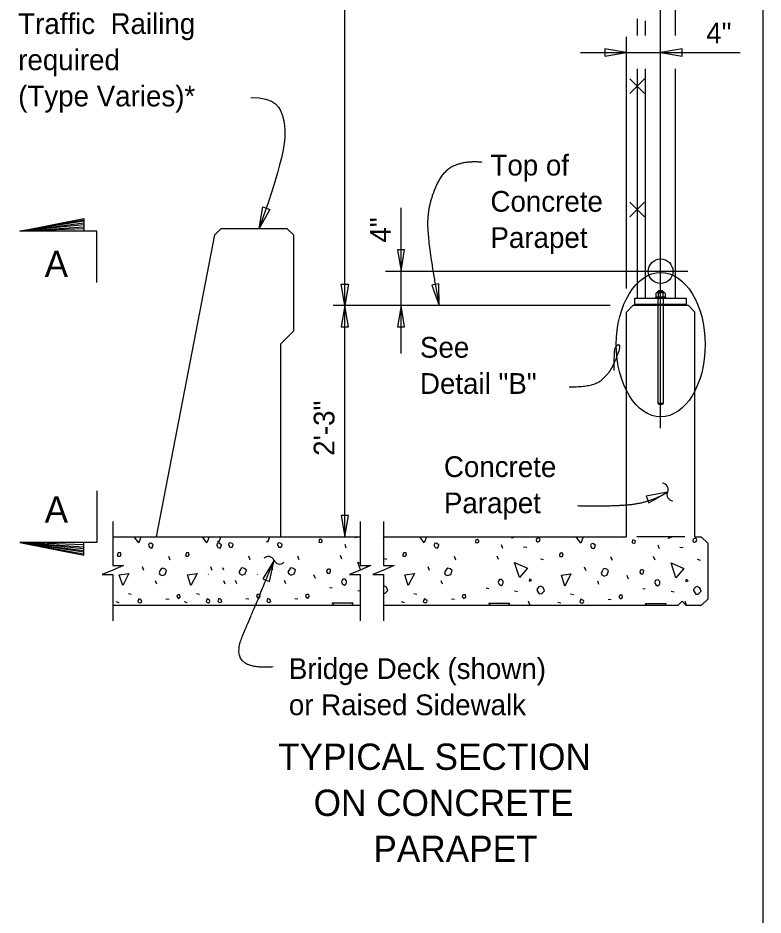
# Model space of a CAD drawing. Extents: x 0 to 72.1, y -15.2 to 30.1.
# Drawn here: x 33.82 to 41.07, y 12.6 to 21.32 of the extents above; entities that cross this region are included whole.
import ezdxf

# ---------------------------------------------------------------- set-up
doc = ezdxf.new("R2010")
doc.units = 0
for name, color, linetype in [('ActivePts-ConstElements', 7, 'Continuous'), ('AdhocPoint_dp', 7, 'Continuous'), ('Border', 7, 'Continuous'), ('Patterning', 7, 'Continuous'), ('PlotBorder_dp', 7, 'Continuous'), ('SheetBorder_dp', 7, 'Continuous'), ('SheetLines_dp', 7, 'Continuous'), ('SupstrConc_h', 7, 'Continuous'), ('TextMisc', 7, 'Continuous')]:
    doc.layers.add(name, color=color, linetype=linetype)

# ---------------------------------------------------------------- blocks, each defined once
blk = doc.blocks.new('Terminator-Arrow')
at = {"layer": 'PlotBorder_dp'}
blk.add_lwpolyline([(0, 0), (-0.00041, 0.000069), (-0.00041, -0.000069), (0, 0)], dxfattribs=at)
blk.add_lwpolyline([(0, 0), (-0.00041, 0.000069), (-0.00041, -0.000069)], close=True, dxfattribs=at)

msp = doc.modelspace()

# ---------------------------------------------------------------- linework, layer by layer
at = {"layer": 'ActivePts-ConstElements'}
msp.add_lwpolyline([(0.016, 2.0538), (41.0666, 2.0538), (41.0666, 27.9999), (0.016, 27.9999)], close=True, dxfattribs=at)
at = {"layer": 'AdhocPoint_dp'}
for p, q in [((39.7989, 18.5283), (39.7364, 18.465)), ((40.3405, 18.5283), (39.7989, 18.5283)), ((40.3405, 18.5283), (39.7989, 18.5283)), ((40.3405, 18.5283), (40.4031, 18.465)), ((39.7364, 16.2784), (39.7364, 18.465)), ((40.4031, 16.2784), (40.4031, 18.465)), ((34.7399, 16.2784), (37.1456, 16.2784)), ((37.3729, 16.2784), (39.7364, 16.2784)), ((40.4031, 16.2784), (40.4656, 16.2784)), ((40.4656, 16.2784), (40.5281, 16.2159)), ((40.5281, 16.2159), (40.5281, 15.6742)), ((40.2364, 15.6117), (40.2781, 15.6533)), ((40.2781, 15.6533), (40.3198, 15.6117)), ((40.5281, 15.6742), (40.4656, 15.6117)), ((40.2364, 15.6117), (37.3729, 15.6117)), ((40.4656, 15.6117), (40.3198, 15.6117))]:
    msp.add_line(p, q, dxfattribs=at)
at = {"layer": 'Border'}
for p, q in [((40.0437, 18.6013), (40.0437, 17.5781)), ((40.0958, 18.6013), (40.0958, 17.5781)), ((40.0437, 17.5781), (40.0958, 17.5781)), ((40.0437, 17.5781), (40.0519, 17.57)), ((40.0519, 17.57), (40.0876, 17.57)), ((40.0958, 17.5781), (40.0876, 17.57))]:
    msp.add_line(p, q, dxfattribs=at)
at = {"layer": 'Patterning'}
for p, q in [((39.9112, 20.7323), (39.7698, 20.5911)), ((39.7698, 20.7323), (39.9112, 20.5911)), ((39.9112, 19.5323), (39.7698, 19.3911)), ((39.7698, 19.5323), (39.9112, 19.3911)), ((40.0586, 18.6707), (40.0793, 18.6707)), ((40.0586, 18.661), (40.0793, 18.661)), ((39.8197, 18.5353), (40.3197, 18.5353)), ((39.8197, 18.5318), (40.3197, 18.5318)), ((35.4069, 16.2784), (35.4083, 16.2781)), ((38.185, 16.2784), (38.1863, 16.2781)), ((39.6911, 16.2784), (39.7101, 16.2746)), ((37.0108, 16.1703), (36.9984, 16.2039)), ((38.5346, 16.1667), (38.5222, 16.2003)), ((38.7343, 16.1826), (38.7662, 16.1791)), ((40.0584, 16.1632), (40.046, 16.1968)), ((40.2581, 16.1791), (40.29, 16.1756)), ((35.2987, 16.0518), (35.2845, 16.0872)), ((36.0762, 16.0554), (36.0621, 16.0907)), ((36.5529, 16.0554), (36.5388, 16.0907)), ((36.9683, 16.0607), (36.9542, 16.096)), ((37.3785, 16.0677), (37.4067, 16.0607)), ((38.0767, 16.0518), (38.0626, 16.0872)), ((38.4922, 16.0571), (38.478, 16.0925)), ((38.9023, 16.0642), (38.9306, 16.0571)), ((39.6005, 16.0483), (39.5864, 16.0836)), ((40.016, 16.0536), (40.0018, 16.0889)), ((40.4261, 16.0607), (40.4544, 16.0536)), ((35.0424, 15.9511), (35.0282, 15.9864)), ((35.7059, 15.9511), (35.6917, 15.9864)), ((35.8199, 15.9546), (35.8104, 15.9783)), ((36.2966, 15.9546), (36.2871, 15.9783)), ((37.8204, 15.9511), (37.8063, 15.9864)), ((39.3442, 15.9475), (39.3301, 15.9829)), ((36.7102, 15.8733), (36.6961, 15.9086)), ((39.7579, 15.8662), (39.7437, 15.9016)), ((35.1679, 15.8185), (35.1555, 15.8521)), ((35.8314, 15.8185), (35.819, 15.8521)), ((35.9454, 15.822), (35.933, 15.8556)), ((36.4221, 15.822), (36.4097, 15.8556)), ((37.9459, 15.8185), (37.9335, 15.8521)), ((39.4697, 15.8149), (39.4573, 15.8485)), ((34.8903, 15.7283), (34.9186, 15.7213)), ((35.5538, 15.7283), (35.5821, 15.7213)), ((36.8481, 15.7849), (36.8729, 15.7814)), ((37.1239, 15.7566), (37.1456, 15.7528)), ((37.6684, 15.7283), (37.6967, 15.7213)), ((38.3719, 15.7814), (38.3967, 15.7778)), ((38.6477, 15.7531), (38.6778, 15.7478)), ((39.1922, 15.7248), (39.2205, 15.7177)), ((39.8958, 15.7778), (39.9205, 15.7743)), ((40.1715, 15.7495), (40.2016, 15.7442)), ((34.7684, 15.6488), (34.7966, 15.6417)), ((35.2563, 15.6771), (35.2863, 15.6718)), ((35.4319, 15.6488), (35.4601, 15.6417)), ((36.0338, 15.6806), (36.0639, 15.6753)), ((36.5105, 15.6806), (36.5405, 15.6753)), ((37.5464, 15.6488), (37.5747, 15.6417)), ((38.0343, 15.6771), (38.0644, 15.6718)), ((38.7962, 15.6187), (38.7838, 15.6523)), ((39.0702, 15.6452), (39.0985, 15.6382)), ((39.5581, 15.6735), (39.5882, 15.6682)), ((40.32, 15.6152), (40.3076, 15.6488))]:
    msp.add_line(p, q, dxfattribs=at)
for points in [[(39.8406, 21.3159), (39.8406, 21.1537)], [(39.8406, 20.8291), (39.8406, 18.6013)], [(34.9911, 16.2215), (34.9479, 16.2784)], [(35.0123, 16.2784), (34.9911, 16.2215)], [(35.6546, 16.2215), (35.6114, 16.2784)], [(35.6758, 16.2784), (35.6546, 16.2215)], [(35.7686, 16.2251), (35.7598, 16.2367)], [(35.7886, 16.2784), (35.7686, 16.2251)], [(36.2453, 16.2251), (36.2365, 16.2367)], [(36.2652, 16.2784), (36.2453, 16.2251)], [(36.7438, 16.2286), (36.7633, 16.2233), (36.7757, 16.2321), (36.7774, 16.2445), (36.7739, 16.248), (36.7597, 16.2551), (36.7474, 16.2534), (36.7456, 16.241), (36.7438, 16.2286)], [(37.0992, 16.2693), (37.102, 16.2784)], [(37.1194, 16.2784), (37.0992, 16.2693)], [(37.3729, 16.2562), (37.3732, 16.2569), (37.3729, 16.2581)], [(37.7691, 16.2215), (37.7259, 16.2784)], [(37.7904, 16.2784), (37.7691, 16.2215)], [(38.2676, 16.2251), (38.2871, 16.2198), (38.2995, 16.2286), (38.3012, 16.241), (38.2977, 16.2445), (38.2836, 16.2516), (38.2712, 16.2498), (38.2694, 16.2374), (38.2676, 16.2251)], [(38.623, 16.2657), (38.6269, 16.2784)], [(38.6511, 16.2784), (38.623, 16.2657)], [(38.8705, 16.2304), (38.8775, 16.2304), (38.8917, 16.2374), (38.897, 16.2534), (38.8952, 16.2622), (38.8811, 16.2693), (38.8634, 16.2587), (38.8598, 16.248), (38.8634, 16.2374), (38.8705, 16.2304)], [(39.2929, 16.218), (39.2471, 16.2784)], [(39.3155, 16.2784), (39.2929, 16.218)], [(39.7915, 16.2215), (39.8109, 16.2162), (39.8233, 16.2251), (39.825, 16.2374), (39.8215, 16.241), (39.8074, 16.248), (39.795, 16.2463), (39.7932, 16.2339), (39.7915, 16.2215)], [(40.1468, 16.2622), (40.1518, 16.2784)], [(40.1828, 16.2784), (40.1468, 16.2622)], [(40.3943, 16.2268), (40.4013, 16.2268), (40.4155, 16.2339), (40.4208, 16.2498), (40.419, 16.2587), (40.4049, 16.2657), (40.3872, 16.2551), (40.3837, 16.2445), (40.3872, 16.2339), (40.3943, 16.2268)], [(35.0901, 16.1897), (35.0989, 16.1738), (35.1201, 16.1703), (35.129, 16.1862), (35.1325, 16.2003), (35.1237, 16.2092), (35.1078, 16.218), (35.0919, 16.2127), (35.0866, 16.1968), (35.0901, 16.1897)], [(35.7536, 16.1897), (35.7624, 16.1738), (35.7836, 16.1703), (35.7925, 16.1862), (35.796, 16.2003), (35.7872, 16.2092), (35.7713, 16.218), (35.7554, 16.2127), (35.7501, 16.1968), (35.7536, 16.1897)], [(35.8676, 16.1932), (35.8765, 16.1773), (35.8977, 16.1738), (35.9065, 16.1897), (35.9101, 16.2039), (35.9012, 16.2127), (35.8853, 16.2215), (35.8694, 16.2162), (35.8641, 16.2003), (35.8676, 16.1932)], [(36.3443, 16.1932), (36.3532, 16.1773), (36.3744, 16.1738), (36.3832, 16.1897), (36.3867, 16.2039), (36.3779, 16.2127), (36.362, 16.2215), (36.3461, 16.2162), (36.3408, 16.2003), (36.3443, 16.1932)], [(37.8681, 16.1897), (37.877, 16.1738), (37.8982, 16.1703), (37.907, 16.1862), (37.9106, 16.2003), (37.9017, 16.2092), (37.8858, 16.218), (37.8699, 16.2127), (37.8646, 16.1968), (37.8681, 16.1897)], [(39.3919, 16.1862), (39.4008, 16.1703), (39.422, 16.1667), (39.4308, 16.1826), (39.4344, 16.1968), (39.4255, 16.2056), (39.4096, 16.2145), (39.3937, 16.2092), (39.3884, 16.1932), (39.3919, 16.1862)], [(34.7878, 16.0925), (34.809, 16.0925), (34.8196, 16.1031), (34.8143, 16.1225), (34.7913, 16.1243), (34.7878, 16.1137), (34.7825, 16.1049), (34.7878, 16.0925), (34.7843, 16.096)], [(35.4513, 16.0925), (35.4725, 16.0925), (35.4831, 16.1031), (35.4778, 16.1225), (35.4548, 16.1243), (35.4513, 16.1137), (35.446, 16.1049), (35.4513, 16.0925), (35.4478, 16.096)], [(37.5658, 16.0925), (37.5871, 16.0925), (37.5977, 16.1031), (37.5924, 16.1225), (37.5694, 16.1243), (37.5658, 16.1137), (37.5605, 16.1049), (37.5658, 16.0925), (37.5623, 16.096)], [(39.0897, 16.0889), (39.1109, 16.0889), (39.1215, 16.0996), (39.1162, 16.119), (39.0932, 16.1208), (39.0897, 16.1102), (39.0844, 16.1013), (39.0897, 16.0889), (39.0861, 16.0925)], [(35.1962, 15.9139), (35.2191, 15.9016), (35.2492, 15.9139), (35.2616, 15.9511), (35.2439, 15.9687), (35.2209, 15.974), (35.2103, 15.967), (35.1979, 15.9475), (35.1891, 15.9316), (35.1962, 15.9139)], [(35.9737, 15.9175), (35.9967, 15.9051), (36.0267, 15.9175), (36.0391, 15.9546), (36.0214, 15.9723), (35.9984, 15.9776), (35.9878, 15.9705), (35.9755, 15.9511), (35.9666, 15.9352), (35.9737, 15.9175)], [(36.4504, 15.9175), (36.4734, 15.9051), (36.5034, 15.9175), (36.5158, 15.9546), (36.4981, 15.9723), (36.4751, 15.9776), (36.4645, 15.9705), (36.4522, 15.9511), (36.4433, 15.9352), (36.4504, 15.9175)], [(37.1483, 15.9574), (37.1239, 16.0324), (37.1456, 16.0229)], [(37.1952, 16.0012), (37.222, 15.9895)], [(37.9742, 15.9139), (37.9972, 15.9016), (38.0272, 15.9139), (38.0396, 15.9511), (38.0219, 15.9687), (37.9989, 15.974), (37.9883, 15.967), (37.976, 15.9475), (37.9671, 15.9316), (37.9742, 15.9139)], [(38.6954, 15.8821), (38.6477, 16.0288), (38.7732, 15.974), (38.6954, 15.8821)], [(39.498, 15.9104), (39.521, 15.898), (39.551, 15.9104), (39.5634, 15.9475), (39.5457, 15.9652), (39.5228, 15.9705), (39.5122, 15.9634), (39.4998, 15.944), (39.4909, 15.9281), (39.498, 15.9104)], [(40.2193, 15.8786), (40.1715, 16.0253), (40.297, 15.9705), (40.2193, 15.8786)], [(34.8355, 15.8043), (34.8019, 15.9086), (34.8956, 15.921), (34.8355, 15.8043)], [(35.499, 15.8043), (35.4654, 15.9086), (35.5591, 15.921), (35.499, 15.8043)], [(35.6692, 15.9168), (35.6663, 15.9112)], [(36.1459, 15.9168), (36.143, 15.9112)], [(36.8198, 15.9405), (36.8287, 15.9245), (36.8481, 15.9263), (36.857, 15.9387), (36.8587, 15.9581), (36.8464, 15.9634), (36.8375, 15.9652), (36.8269, 15.9617), (36.8234, 15.9581), (36.8198, 15.9405)], [(37.6136, 15.8043), (37.58, 15.9086), (37.6737, 15.921), (37.6136, 15.8043)], [(39.1374, 15.8008), (39.1038, 15.9051), (39.1975, 15.9175), (39.1374, 15.8008)], [(39.8675, 15.9334), (39.8763, 15.9175), (39.8958, 15.9192), (39.9046, 15.9316), (39.9064, 15.9511), (39.894, 15.9564), (39.8851, 15.9581), (39.8745, 15.9546), (39.871, 15.9511), (39.8675, 15.9334)], [(36.9648, 15.8415), (36.9754, 15.8202), (36.9931, 15.8096), (37.0072, 15.8202), (37.0143, 15.8309), (37.0143, 15.8521), (36.9984, 15.868), (36.9789, 15.8662), (36.9701, 15.8574), (36.9648, 15.8415)], [(37.3729, 15.729), (37.3873, 15.7301), (37.3961, 15.7389), (37.4156, 15.7584), (37.4032, 15.7884), (37.3785, 15.8026), (37.3729, 15.8004)], [(38.4886, 15.8379), (38.4992, 15.8167), (38.5169, 15.8061), (38.531, 15.8167), (38.5381, 15.8273), (38.5381, 15.8485), (38.5222, 15.8644), (38.5028, 15.8627), (38.4939, 15.8538), (38.4886, 15.8379)], [(38.7944, 15.8468), (38.8139, 15.8556), (38.8068, 15.8627), (38.7944, 15.868), (38.7891, 15.8556), (38.7944, 15.8468)], [(38.8651, 15.7619), (38.8881, 15.7248), (38.9111, 15.7266), (38.9199, 15.7354), (38.9394, 15.7548), (38.927, 15.7849), (38.9023, 15.799), (38.8846, 15.792), (38.8705, 15.7778), (38.8651, 15.7619)], [(40.0124, 15.8344), (40.023, 15.8132), (40.0407, 15.8026), (40.0549, 15.8132), (40.0619, 15.8238), (40.0619, 15.845), (40.046, 15.8609), (40.0266, 15.8591), (40.0177, 15.8503), (40.0124, 15.8344)], [(40.3183, 15.8432), (40.3377, 15.8521), (40.3306, 15.8591), (40.3183, 15.8644), (40.3129, 15.8521), (40.3183, 15.8432)], [(40.389, 15.7584), (40.4119, 15.7213), (40.4349, 15.723), (40.4438, 15.7319), (40.4632, 15.7513), (40.4508, 15.7814), (40.4261, 15.7955), (40.4084, 15.7884), (40.3943, 15.7743), (40.389, 15.7584)], [(35.3676, 15.6894), (35.3782, 15.6788), (35.3888, 15.6859), (35.3959, 15.6965), (35.3924, 15.7142), (35.3835, 15.7159), (35.3712, 15.7142), (35.3606, 15.7036), (35.3676, 15.6894)], [(36.1452, 15.693), (36.1558, 15.6824), (36.1664, 15.6894), (36.1735, 15.7), (36.1699, 15.7177), (36.1611, 15.7195), (36.1487, 15.7177), (36.1381, 15.7071), (36.1452, 15.693)], [(36.6219, 15.693), (36.6325, 15.6824), (36.6431, 15.6894), (36.6501, 15.7), (36.6466, 15.7177), (36.6378, 15.7195), (36.6254, 15.7177), (36.6148, 15.7071), (36.6219, 15.693)], [(38.1457, 15.6894), (38.1563, 15.6788), (38.1669, 15.6859), (38.174, 15.6965), (38.1704, 15.7142), (38.1616, 15.7159), (38.1492, 15.7142), (38.1386, 15.7036), (38.1457, 15.6894)], [(39.6695, 15.6859), (39.6801, 15.6753), (39.6907, 15.6824), (39.6978, 15.693), (39.6942, 15.7106), (39.6854, 15.7124), (39.673, 15.7106), (39.6624, 15.7), (39.6695, 15.6859)], [(34.9929, 15.6399), (35.0052, 15.6382), (35.0176, 15.6435), (35.0211, 15.6541), (35.0158, 15.6629), (35.0052, 15.67), (34.9929, 15.6753), (34.9858, 15.6611), (34.9823, 15.6505), (34.9929, 15.6399)], [(35.6564, 15.6399), (35.6687, 15.6382), (35.6811, 15.6435), (35.6846, 15.6541), (35.6793, 15.6629), (35.6687, 15.67), (35.6564, 15.6753), (35.6493, 15.6611), (35.6458, 15.6505), (35.6564, 15.6399)], [(35.7704, 15.6435), (35.7828, 15.6417), (35.7952, 15.647), (35.7987, 15.6576), (35.7934, 15.6665), (35.7828, 15.6735), (35.7704, 15.6788), (35.7633, 15.6647), (35.7598, 15.6541)], [(35.7598, 15.6541), (35.7704, 15.6435)], [(36.2471, 15.6435), (36.2595, 15.6417), (36.2718, 15.647), (36.2754, 15.6576), (36.2701, 15.6665), (36.2595, 15.6735), (36.2471, 15.6788), (36.24, 15.6647), (36.2365, 15.6541)], [(36.2365, 15.6541), (36.2471, 15.6435)], [(36.8948, 15.6117), (36.8746, 15.6382), (37.0744, 15.6364), (37.0652, 15.6117)], [(37.7709, 15.6399), (37.7833, 15.6382), (37.7957, 15.6435), (37.7992, 15.6541), (37.7939, 15.6629), (37.7833, 15.67), (37.7709, 15.6753), (37.7638, 15.6611), (37.7603, 15.6505), (37.7709, 15.6399)], [(38.4159, 15.6117), (38.3985, 15.6346), (38.5982, 15.6329), (38.5903, 15.6117)], [(39.2947, 15.6364), (39.3071, 15.6346), (39.3195, 15.6399), (39.323, 15.6505), (39.3177, 15.6594), (39.3071, 15.6665), (39.2947, 15.6718), (39.2876, 15.6576), (39.2841, 15.647), (39.2947, 15.6364)], [(39.9371, 15.6117), (39.9223, 15.6311), (40.122, 15.6293), (40.1154, 15.6117)]]:
    msp.add_lwpolyline(points, dxfattribs=at)
msp.add_lwpolyline([(39.8197, 18.5388), (40.3197, 18.5388), (40.3197, 18.5284), (39.8197, 18.5284)], close=True, dxfattribs=at)
at = {"layer": 'PlotBorder_dp'}
for p, q in [((36.9957, 16.2784), (36.9957, 24.8617)), ((39.7364, 18.694), (39.7364, 21.1397)), ((39.2898, 20.9897), (40.8444, 20.9897)), ((37.5436, 18.063), (37.5436, 19.4799)), ((33.8335, 19.2512), (34.4585, 19.3612)), ((34.4585, 19.3479), (33.8335, 19.2512)), ((33.8335, 19.2512), (34.4585, 19.3312)), ((34.4585, 19.3129), (33.8335, 19.2512)), ((33.8335, 19.2512), (34.4585, 19.2945)), ((34.4585, 19.2745), (33.8335, 19.2512)), ((40.0697, 18.609), (40.0697, 18.6083)), ((39.5803, 18.5284), (36.8819, 18.5284)), ((34.4585, 16.2016), (33.8335, 16.2249)), ((33.8335, 16.2249), (34.4585, 16.1816)), ((34.4585, 16.1633), (33.8335, 16.2249)), ((33.8335, 16.2249), (34.4585, 16.1449)), ((34.4585, 16.1283), (33.8335, 16.2249)), ((33.8335, 16.2249), (34.4585, 16.1149))]:
    msp.add_line(p, q, dxfattribs=at)
for points in [[(39.7364, 20.9897), (39.5282, 21.025), (39.5282, 20.9544)], [(40.0697, 20.9897), (40.278, 20.9544), (40.278, 21.025)], [(37.5436, 18.8617), (37.5789, 19.0699), (37.5083, 19.0699)], [(36.9957, 18.5284), (36.9604, 18.7366), (37.031, 18.7366)], [(37.9143, 18.5284), (37.9118, 18.7396), (37.8424, 18.727)], [(36.9957, 18.5284), (36.9604, 18.3201), (37.031, 18.3201)], [(37.5436, 18.5284), (37.5083, 18.3201), (37.5789, 18.3201)], [(40.1374, 16.7145), (39.93, 16.6749), (39.9546, 16.6088)], [(36.9957, 16.2784), (37.031, 16.4866), (36.9604, 16.4866)], [(36.3076, 16.0507), (36.1991, 15.8695), (36.2649, 15.8439)]]:
    msp.add_lwpolyline(points, close=True, dxfattribs=at)
for points in [[(34.5835, 18.7512), (34.5835, 19.2512), (33.8335, 19.2512), (34.4585, 19.3762), (34.4585, 19.2512)], [(34.5835, 16.7249), (34.5835, 16.2249), (33.8335, 16.2249), (34.4585, 16.0999), (34.4585, 16.2249)], [(34.7399, 16.4284), (34.7399, 16.0012), (34.8432, 16.0012), (34.7399, 15.9562), (34.6365, 15.9112), (34.7399, 15.9112), (34.7399, 15.4617)], [(37.1456, 16.4284), (37.1456, 16.0012), (37.249, 16.0012), (37.1456, 15.9562), (37.0423, 15.9112), (37.1456, 15.9112), (37.1456, 15.4617)], [(37.3729, 16.4284), (37.3729, 16.0012), (37.4763, 16.0012), (37.3729, 15.9562), (37.2696, 15.9112), (37.3729, 15.9112), (37.3729, 15.4617)]]:
    msp.add_lwpolyline(points, dxfattribs=at)
for centre, start, end in [((40.0832, 16.7407), 334.61622, 86.34344), ((40.1909, 16.6896), 154.61622, 266.34344), ((36.252, 16.0277), 22.88008, 134.6073), ((36.3619, 16.0741), 202.88008, 314.6073)]:
    msp.add_arc(centre, 0.0596, start, end, dxfattribs=at)
msp.add_ellipse((40.071, 18.1482), major_axis=(0, 0.7024), ratio=0.61552, dxfattribs=at)
for points, degree in [([(36.0807, 20.5498), (36.3226, 20.5557), (36.4287, 20.3667), (36.4287, 20.0125), (36.1633, 19.2784)], 3), ([(38.3343, 19.9207), (38.0205, 19.9513), (37.8022, 19.5356), (37.8022, 19.1164), (37.9143, 18.5284)], 2), ([(39.1809, 17.7384), (39.4075, 17.7344), (39.578, 17.8693), (39.6731, 18.0995), (39.6731, 18.1512), (39.6359, 18.1364), (39.6137, 18.0836), (39.6151, 17.8968)], 2), ([(39.262, 16.5822), (39.6006, 16.574), (39.9722, 16.6153), (40.1374, 16.7145)], 2), ([(36.2986, 15.0134), (36.0666, 14.9967), (35.9307, 15.1557), (36.0812, 15.4988), (36.3076, 16.0507)], 2)]:
    msp.add_open_spline(points, degree=degree, dxfattribs=at)
at = {"layer": 'SheetBorder_dp'}
for p, q in [((40.0698, 17.3367), (40.0698, 21.5561)), ((37.3936, 18.8617), (40.3354, 18.8617))]:
    msp.add_line(p, q, dxfattribs=at)
at = {"layer": 'SupstrConc_h'}
for p, q in [((35.163, 16.2784), (35.7323, 19.2158)), ((35.7323, 19.2158), (35.7948, 19.2783)), ((35.7948, 19.2783), (36.4338, 19.2784)), ((36.4338, 19.2783), (36.4963, 19.2158)), ((36.4963, 19.2158), (36.4963, 18.2783)), ((36.4963, 18.2783), (36.3713, 18.1533)), ((36.3713, 18.1533), (36.3713, 16.2784)), ((40.3045, 16.2784), (39.8394, 16.2784)), ((37.1456, 15.6117), (34.7399, 15.6117))]:
    msp.add_line(p, q, dxfattribs=at)
at = {"layer": 'TextMisc'}
for p, q in [((40.2156, 21.1537), (40.2156, 24.8617)), ((39.9239, 21.1537), (39.9239, 21.2978)), ((39.9239, 18.6013), (39.9239, 20.8291)), ((40.2156, 18.6013), (40.2156, 20.8291)), ((40.0537, 18.6756), (40.044, 18.6659)), ((40.0537, 18.6756), (40.0842, 18.6756)), ((40.0842, 18.6756), (40.0955, 18.6659)), ((40.0201, 18.6083), (40.0201, 18.6012)), ((40.0201, 18.6083), (40.1195, 18.6083)), ((40.0243, 18.6459), (40.0243, 18.6083)), ((40.1151, 18.6083), (40.0243, 18.6083)), ((40.1038, 18.6546), (40.0357, 18.6546)), ((40.044, 18.6659), (40.044, 18.6546)), ((40.044, 18.6659), (40.0955, 18.6659)), ((40.047, 18.6462), (40.047, 18.6083)), ((40.0924, 18.6462), (40.0924, 18.6083)), ((40.0955, 18.6659), (40.0955, 18.6546)), ((40.1151, 18.6459), (40.1151, 18.6083)), ((40.1195, 18.6083), (40.1195, 18.6012)), ((39.95, 18.5388), (40.1895, 18.5388))]:
    msp.add_line(p, q, dxfattribs=at)
msp.add_lwpolyline([(39.8197, 18.6013), (40.3197, 18.6013), (40.3197, 18.5388), (39.8197, 18.5388)], close=True, dxfattribs=at)
msp.add_circle((40.0698, 18.8617), 0.1198, dxfattribs=at)
for centre, radius, start, end in [((40.0357, 18.6428), 0.0118, 16.59863, 164.70054), ((40.0697, 18.6199), 0.0347, 49.20147, 130.79853), ((40.1037, 18.6429), 0.0118, 15.15064, 163.50417)]:
    msp.add_arc(centre, radius, start, end, dxfattribs=at)

# ---------------------------------------------------------------- block references
at = {"layer": 'PlotBorder_dp', "xscale": 507.9999699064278, "yscale": -507.99996990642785, "rotation": -109.44616743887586}
msp.add_blockref('Terminator-Arrow', (36.1633, 19.2784), dxfattribs=at)

# ---------------------------------------------------------------- texts
at = {"layer": 'PlotBorder_dp'}
for s, height, p in [('Traffic  Railing', 0.2016, (33.8184, 21.1688)), ('required', 0.2016, (33.8184, 20.8168)), ('(Type Varies)*', 0.2016, (33.8184, 20.4648)), ('Top of ', 0.2016, (38.4139, 19.7926)), ('Concrete', 0.2016, (38.4139, 19.4406)), ('Parapet', 0.2016, (38.4139, 19.0886)), ('See ', 0.2016, (37.7279, 18.0211)), ('Detail "B"', 0.2016, (37.7279, 17.6691)), ('Concrete', 0.2016, (37.9608, 16.8603)), ('Parapet', 0.2016, (37.9608, 16.5083)), ('Bridge Deck (shown)', 0.2016, (36.4522, 14.8966)), ('or Raised Sidewalk', 0.2016, (36.4522, 14.5446)), ('TYPICAL SECTION', 0.256001, (36.3475, 14.0127)), ('ON CONCRETE', 0.256001, (36.6929, 13.5647)), ('PARAPET', 0.256, (37.2744, 13.1167))]:
    msp.add_text(s, height=height, dxfattribs=at).set_placement(p)
at = {"layer": 'SheetLines_dp'}
for s, height, p in [('4"', 0.2016, (40.5134, 21.0766)), ('A', 0.256, (34.0756, 18.8045)), ('A', 0.256, (34.0756, 16.4158))]:
    msp.add_text(s, height=height, dxfattribs=at).set_placement(p)
for s, p in [('4"', (37.4439, 19.1402)), ('2\'-3"', (36.8957, 17.0665))]:
    msp.add_text(s, height=0.2016, rotation=90, dxfattribs=at).set_placement(p)

doc.saveas('drawing.dxf')
